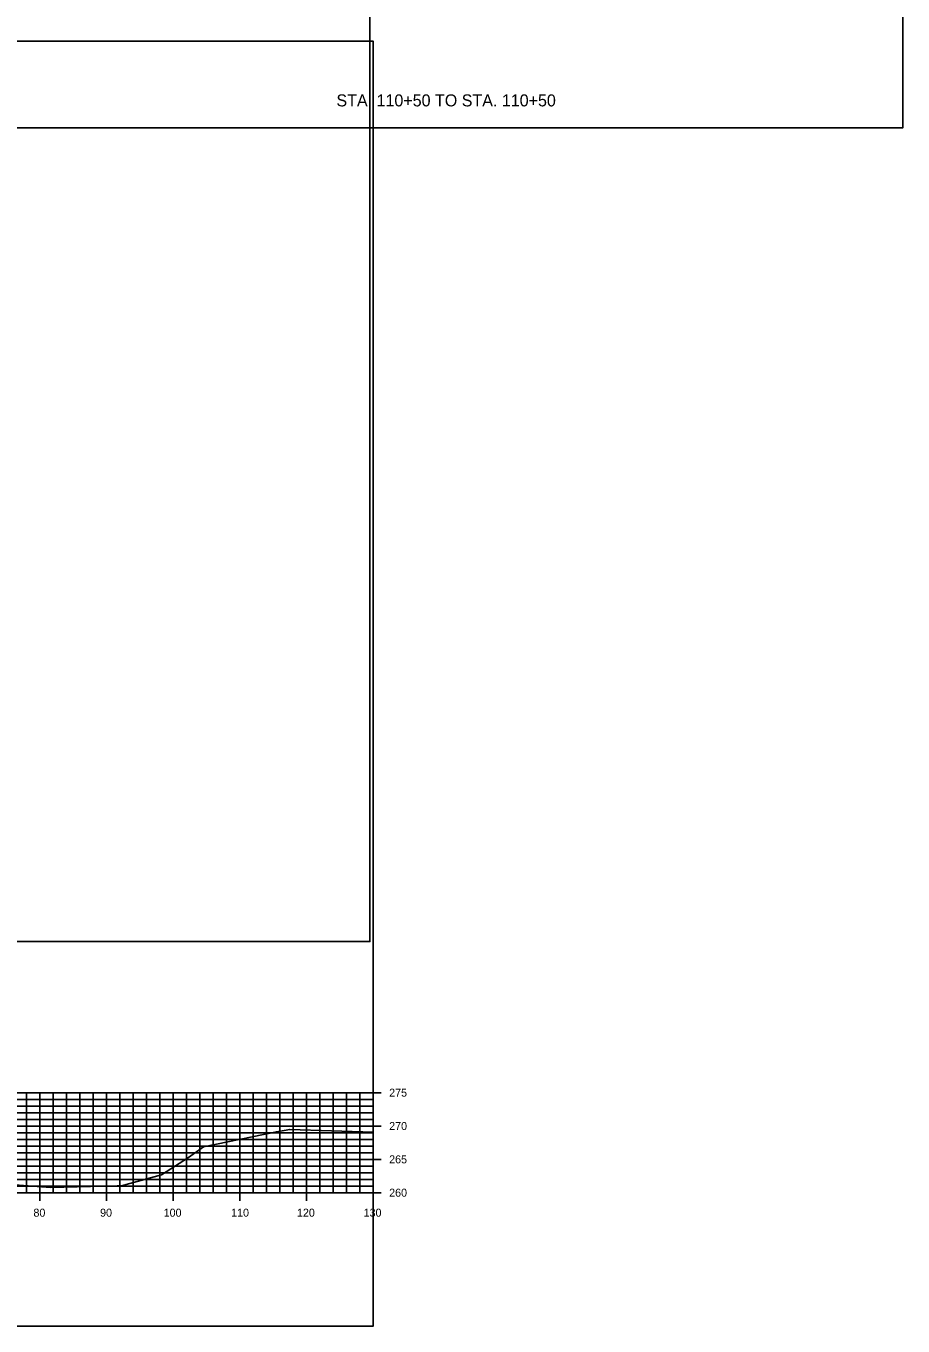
# Model space of a CAD drawing. Extents: x 1661012 to 1662122, y 670053 to 671852.
# Drawn here: x 1661985.4 to 1662117, y 671480 to 671675 of the extents above; entities that cross this region are included whole.
import ezdxf

# ---------------------------------------------------------------- set-up
doc = ezdxf.new("R2010")
doc.units = 0
for name, color, linetype in [('R_Concrete', 7, 'Continuous'), ('R_Concrete Hidden', 7, 'Continuous'), ('R_Erosion', 7, 'Continuous'), ('R_Exist Surface', 7, 'Continuous'), ('R_Proposed Road', 7, 'Continuous')]:
    doc.layers.add(name, color=color, linetype=linetype)

msp = doc.modelspace()

# ---------------------------------------------------------------- linework, layer by layer
at = {"layer": 'R_Concrete'}
for p, q in [((1661707.5, 671514.96), (1662037.5, 671514.96)), ((1661985.5, 671499.96), (1661985.5, 671514.96)), ((1661987.5, 671499.96), (1661987.5, 671514.96)), ((1661989.5, 671499.96), (1661989.5, 671514.96)), ((1661991.5, 671499.96), (1661991.5, 671514.96)), ((1661993.5, 671499.96), (1661993.5, 671514.96)), ((1661995.5, 671499.96), (1661995.5, 671514.96)), ((1661997.5, 671499.96), (1661997.5, 671514.96)), ((1661999.5, 671499.96), (1661999.5, 671514.96)), ((1662001.5, 671499.96), (1662001.5, 671514.96)), ((1662003.5, 671499.96), (1662003.5, 671514.96)), ((1662005.5, 671499.96), (1662005.5, 671514.96)), ((1662007.5, 671499.96), (1662007.5, 671514.96)), ((1662009.5, 671499.96), (1662009.5, 671514.96)), ((1662011.5, 671499.96), (1662011.5, 671514.96)), ((1662013.5, 671499.96), (1662013.5, 671514.96)), ((1662015.5, 671499.96), (1662015.5, 671514.96)), ((1662017.5, 671499.96), (1662017.5, 671514.96)), ((1662019.5, 671499.96), (1662019.5, 671514.96)), ((1662021.5, 671499.96), (1662021.5, 671514.96)), ((1662023.5, 671499.96), (1662023.5, 671514.96)), ((1662025.5, 671499.96), (1662025.5, 671514.96)), ((1662027.5, 671499.96), (1662027.5, 671514.96)), ((1662029.5, 671499.96), (1662029.5, 671514.96)), ((1662031.5, 671499.96), (1662031.5, 671514.96)), ((1662033.5, 671499.96), (1662033.5, 671514.96)), ((1662035.5, 671499.96), (1662035.5, 671514.96)), ((1662038.7, 671514.96), (1662036.3, 671514.96)), ((1662037.5, 671499.96), (1662037.5, 671514.96)), ((1661707.5, 671513.96), (1662037.5, 671513.96)), ((1661707.5, 671512.96), (1662037.5, 671512.96)), ((1662037.5, 671513.96), (1662036.9, 671513.96)), ((1662037.5, 671512.96), (1662036.9, 671512.96)), ((1661707.5, 671511.96), (1662037.5, 671511.96)), ((1661707.5, 671510.96), (1662037.5, 671510.96)), ((1662037.5, 671511.96), (1662036.9, 671511.96)), ((1662037.5, 671510.96), (1662036.9, 671510.96)), ((1661707.5, 671509.96), (1662037.5, 671509.96)), ((1661707.5, 671508.96), (1662037.5, 671508.96)), ((1662038.7, 671509.96), (1662036.3, 671509.96)), ((1662037.5, 671508.96), (1662036.9, 671508.96)), ((1661707.5, 671507.96), (1662037.5, 671507.96)), ((1661707.5, 671506.96), (1662037.5, 671506.96)), ((1662037.5, 671507.96), (1662036.9, 671507.96)), ((1662037.5, 671506.96), (1662036.9, 671506.96)), ((1661707.5, 671505.96), (1662037.5, 671505.96)), ((1661707.5, 671504.96), (1662037.5, 671504.96)), ((1662038.7, 671504.96), (1662036.3, 671504.96)), ((1662037.5, 671505.96), (1662036.9, 671505.96)), ((1661707.5, 671503.96), (1662037.5, 671503.96)), ((1661707.5, 671502.96), (1662037.5, 671502.96)), ((1662037.5, 671503.96), (1662036.9, 671503.96)), ((1662037.5, 671502.96), (1662036.9, 671502.96)), ((1661707.5, 671501.96), (1662037.5, 671501.96)), ((1661707.5, 671500.96), (1662037.5, 671500.96)), ((1661985.5, 671499.96), (1661985.5, 671500.56)), ((1661987.5, 671498.76), (1661987.5, 671501.16)), ((1661989.5, 671499.96), (1661989.5, 671500.56)), ((1661991.5, 671499.96), (1661991.5, 671500.56)), ((1661993.5, 671499.96), (1661993.5, 671500.56)), ((1661995.5, 671499.96), (1661995.5, 671500.56)), ((1661997.5, 671498.76), (1661997.5, 671501.16)), ((1661999.5, 671499.96), (1661999.5, 671500.56)), ((1662001.5, 671499.96), (1662001.5, 671500.56)), ((1662003.5, 671499.96), (1662003.5, 671500.56)), ((1662005.5, 671499.96), (1662005.5, 671500.56)), ((1662007.5, 671498.76), (1662007.5, 671501.16)), ((1662009.5, 671499.96), (1662009.5, 671500.56)), ((1662011.5, 671499.96), (1662011.5, 671500.56)), ((1662013.5, 671499.96), (1662013.5, 671500.56)), ((1662015.5, 671499.96), (1662015.5, 671500.56)), ((1662017.5, 671498.76), (1662017.5, 671501.16)), ((1662019.5, 671499.96), (1662019.5, 671500.56)), ((1662021.5, 671499.96), (1662021.5, 671500.56)), ((1662023.5, 671499.96), (1662023.5, 671500.56)), ((1662025.5, 671499.96), (1662025.5, 671500.56)), ((1662027.5, 671498.76), (1662027.5, 671501.16)), ((1662029.5, 671499.96), (1662029.5, 671500.56)), ((1662031.5, 671499.96), (1662031.5, 671500.56)), ((1662033.5, 671499.96), (1662033.5, 671500.56)), ((1662035.5, 671499.96), (1662035.5, 671500.56)), ((1662037.5, 671501.96), (1662036.9, 671501.96)), ((1662037.5, 671500.96), (1662036.9, 671500.96)), ((1662037.5, 671498.76), (1662037.5, 671501.16)), ((1661707.5, 671499.96), (1662037.5, 671499.96)), ((1662038.7, 671499.96), (1662036.3, 671499.96))]:
    msp.add_line(p, q, dxfattribs=at)
at = {"layer": 'R_Erosion'}
msp.add_lwpolyline([(1661981.01, 671501.35), (1661989.09, 671500.73), (1661999.08, 671500.98), (1661999.76, 671501), (1662000.43, 671501.17), (1662005.74, 671502.66), (1662009.8, 671505.25), (1662012.06, 671506.84), (1662022.99, 671509.11), (1662024.98, 671509.45), (1662037.5, 671509.02)], dxfattribs=at)
at = {"layer": 'R_Exist Surface'}
for p, q in [((1662037.5, 671499.96), (1662037.5, 671514.96)), ((1661707.5, 671499.96), (1662037.5, 671499.96))]:
    msp.add_line(p, q, dxfattribs=at)
at = {"layer": 'R_Proposed Road'}
for points in [[(1661756.99, 671659.7), (1662116.99, 671659.7), (1662116.99, 671852.4), (1661756.99, 671852.4)], [(1661677.02, 671537.62), (1662037.02, 671537.62), (1662037.02, 671730.32), (1661677.02, 671730.32)], [(1661677.5, 671479.96), (1662037.5, 671479.96), (1662037.5, 671672.66), (1661677.5, 671672.66)]]:
    msp.add_lwpolyline(points, close=True, dxfattribs=at)

# ---------------------------------------------------------------- texts
at = {"layer": 'R_Concrete Hidden'}
for s, height, p in [('STA. 110+50 TO STA. 110+50', 1.8, (1662031.99, 671662.9)), ('STA. 110+50 TO STA. 110+50', 1.8, (1662031.99, 671662.9)), ('275', 1.2, (1662039.9, 671514.36)), ('270', 1.2, (1662039.9, 671509.36)), ('265', 1.2, (1662039.9, 671504.36)), ('260', 1.2, (1662039.9, 671499.36)), ('80', 1.2, (1661986.53, 671496.36)), ('90', 1.2, (1661996.53, 671496.36)), ('100', 1.2, (1662006.07, 671496.36)), ('110', 1.2, (1662016.19, 671496.36)), ('120', 1.2, (1662026.07, 671496.36)), ('130', 1.2, (1662036.07, 671496.36))]:
    msp.add_text(s, height=height, dxfattribs=at).set_placement(p)

doc.saveas('drawing.dxf')
